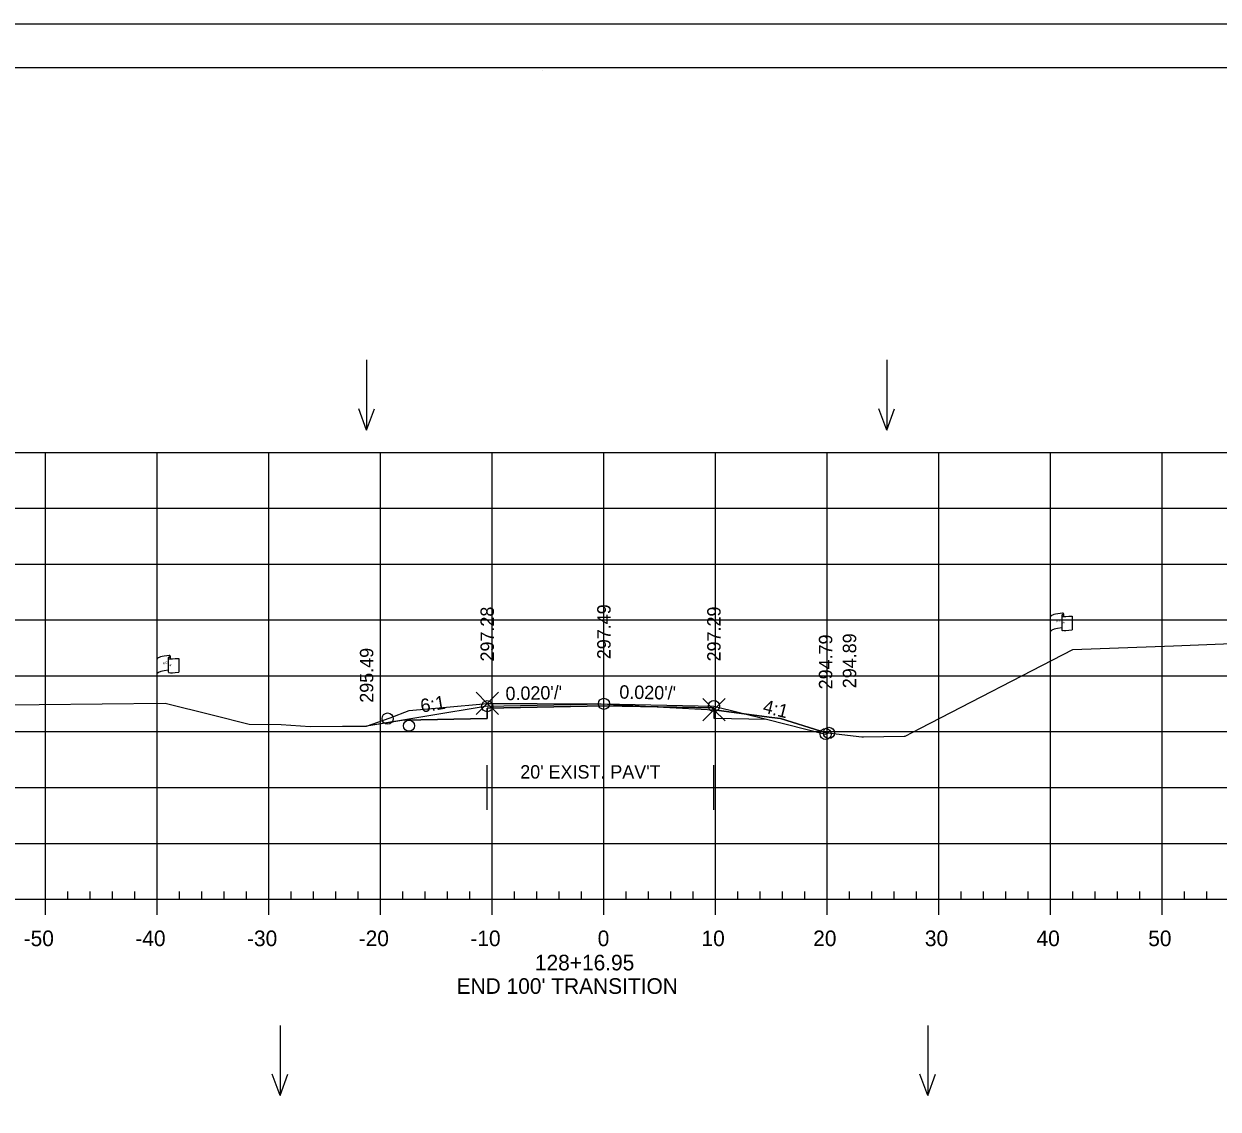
# Model space of a CAD drawing. Extents: x 1370843 to 1371177, y 380307 to 382654.
# Drawn here: x 1370961.8 to 1371068.7, y 382557 to 382654.2 of the extents above; entities that cross this region are included whole.
import ezdxf

# ---------------------------------------------------------------- set-up
doc = ezdxf.new("R2010")
doc.units = 0
for name, color, linetype in [('R_Axis', 7, 'Continuous'), ('R_Axis Annot', 7, 'Continuous'), ('R_Border', 7, 'Continuous'), ('R_Exist Surface', 7, 'Continuous'), ('R_Exist Surface Annot', 7, 'Continuous'), ('R_Fin Surface Annot', 7, 'Continuous'), ('R_Grid', 7, 'Continuous'), ('R_No Plot', 7, 'Continuous'), ('R_ROW', 7, 'Continuous'), ('R_Water Annot', 7, 'Continuous')]:
    doc.layers.add(name, color=color, linetype=linetype)

msp = doc.modelspace()

# ---------------------------------------------------------------- linework, layer by layer
at = {"layer": 'R_Axis'}
for p, q in [((1370868.71, 382575.83), (1371158.71, 382575.83)), ((1370963.71, 382574.43), (1370963.71, 382575.83)), ((1370965.71, 382575.83), (1370965.71, 382576.53)), ((1370967.71, 382575.83), (1370967.71, 382576.53)), ((1370969.71, 382575.83), (1370969.71, 382576.53)), ((1370971.71, 382575.83), (1370971.71, 382576.53)), ((1370973.71, 382574.43), (1370973.71, 382575.83)), ((1370975.71, 382575.83), (1370975.71, 382576.53)), ((1370977.71, 382575.83), (1370977.71, 382576.53)), ((1370979.71, 382575.83), (1370979.71, 382576.53)), ((1370981.71, 382575.83), (1370981.71, 382576.53)), ((1370983.71, 382574.43), (1370983.71, 382575.83)), ((1370985.71, 382575.83), (1370985.71, 382576.53)), ((1370987.71, 382575.83), (1370987.71, 382576.53)), ((1370989.71, 382575.83), (1370989.71, 382576.53)), ((1370991.71, 382575.83), (1370991.71, 382576.53)), ((1370993.71, 382574.43), (1370993.71, 382575.83)), ((1370995.71, 382575.83), (1370995.71, 382576.53)), ((1370997.71, 382575.83), (1370997.71, 382576.53)), ((1370999.71, 382575.83), (1370999.71, 382576.53)), ((1371001.71, 382575.83), (1371001.71, 382576.53)), ((1371003.71, 382574.43), (1371003.71, 382575.83)), ((1371005.71, 382575.83), (1371005.71, 382576.53)), ((1371007.71, 382575.83), (1371007.71, 382576.53)), ((1371009.71, 382575.83), (1371009.71, 382576.53)), ((1371011.71, 382575.83), (1371011.71, 382576.53)), ((1371013.71, 382574.43), (1371013.71, 382575.83)), ((1371015.71, 382575.83), (1371015.71, 382576.53)), ((1371017.71, 382575.83), (1371017.71, 382576.53)), ((1371019.71, 382575.83), (1371019.71, 382576.53)), ((1371021.71, 382575.83), (1371021.71, 382576.53)), ((1371023.71, 382574.43), (1371023.71, 382575.83)), ((1371025.71, 382575.83), (1371025.71, 382576.53)), ((1371027.71, 382575.83), (1371027.71, 382576.53)), ((1371029.71, 382575.83), (1371029.71, 382576.53)), ((1371031.71, 382575.83), (1371031.71, 382576.53)), ((1371033.71, 382574.43), (1371033.71, 382575.83)), ((1371035.71, 382575.83), (1371035.71, 382576.53)), ((1371037.71, 382575.83), (1371037.71, 382576.53)), ((1371039.71, 382575.83), (1371039.71, 382576.53)), ((1371041.71, 382575.83), (1371041.71, 382576.53)), ((1371043.71, 382574.43), (1371043.71, 382575.83)), ((1371045.71, 382575.83), (1371045.71, 382576.53)), ((1371047.71, 382575.83), (1371047.71, 382576.53)), ((1371049.71, 382575.83), (1371049.71, 382576.53)), ((1371051.71, 382575.83), (1371051.71, 382576.53)), ((1371053.71, 382574.43), (1371053.71, 382575.83)), ((1371055.71, 382575.83), (1371055.71, 382576.53)), ((1371057.71, 382575.83), (1371057.71, 382576.53)), ((1371059.71, 382575.83), (1371059.71, 382576.53)), ((1371061.71, 382575.83), (1371061.71, 382576.53)), ((1371063.71, 382574.43), (1371063.71, 382575.83)), ((1371065.71, 382575.83), (1371065.71, 382576.53)), ((1371067.71, 382575.83), (1371067.71, 382576.53))]:
    msp.add_line(p, q, dxfattribs=at)
at = {"layer": 'R_Border'}
for p, q in [((1370855.71, 382650.29), (1371171.89, 382650.29)), ((1371008.23, 382650.03), (1371008.23, 382650.03)), ((1371008.23, 382650.03), (1371008.23, 382650.03))]:
    msp.add_line(p, q, dxfattribs=at)
at = {"layer": 'R_Exist Surface'}
msp.add_lwpolyline([(1370954.77, 382593.19), (1370963.15, 382593.25), (1370974.42, 382593.39), (1370978.64, 382592.34), (1370981.93, 382591.51), (1370984.8, 382591.47), (1370987.41, 382591.3), (1370990.31, 382591.31), (1370992.46, 382591.32), (1370994.57, 382592.08), (1370996.27, 382592.73), (1370999.29, 382593), (1371003.26, 382593.36), (1371007.74, 382593.34), (1371013.45, 382593.33), (1371019.06, 382593.03), (1371023.56, 382592.79), (1371028.76, 382592.1), (1371029.51, 382592), (1371033.12, 382590.87), (1371033.5, 382590.76), (1371036.81, 382590.38), (1371036.94, 382590.36), (1371040.61, 382590.43), (1371040.68, 382590.43), (1371042.07, 382591.14), (1371055.69, 382598.19), (1371064.7, 382598.52), (1371098.98, 382599.88)], dxfattribs=at)
at = {"layer": 'R_Exist Surface Annot'}
for p, q in [((1371003.26, 382583.83), (1371003.26, 382587.83)), ((1371023.56, 382583.83), (1371023.56, 382587.83)), ((1371003.26, 382585.83), (1371023.56, 382585.83))]:
    msp.add_line(p, q, dxfattribs=at)
at = {"layer": 'R_Grid'}
for p, q in [((1370868.71, 382615.83), (1371158.71, 382615.83)), ((1370963.71, 382575.83), (1370963.71, 382615.83)), ((1370973.71, 382575.83), (1370973.71, 382615.83)), ((1370983.71, 382575.83), (1370983.71, 382615.83)), ((1370993.71, 382575.83), (1370993.71, 382615.83)), ((1371003.71, 382575.83), (1371003.71, 382615.83)), ((1371013.71, 382575.83), (1371013.71, 382615.83)), ((1371023.71, 382575.83), (1371023.71, 382615.83)), ((1371033.71, 382575.83), (1371033.71, 382615.83)), ((1371043.71, 382575.83), (1371043.71, 382615.83)), ((1371053.71, 382575.83), (1371053.71, 382615.83)), ((1371063.71, 382575.83), (1371063.71, 382615.83)), ((1370868.71, 382610.83), (1371158.71, 382610.83)), ((1370868.71, 382605.83), (1371158.71, 382605.83)), ((1370868.71, 382600.83), (1371158.71, 382600.83)), ((1370868.71, 382595.83), (1371158.71, 382595.83)), ((1370868.71, 382590.83), (1371158.71, 382590.83)), ((1370868.71, 382585.83), (1371158.71, 382585.83)), ((1370868.71, 382580.83), (1371158.71, 382580.83)), ((1370868.71, 382575.83), (1371158.71, 382575.83))]:
    msp.add_line(p, q, dxfattribs=at)
at = {"layer": 'R_No Plot'}
for p, q in [((1370843.31, 382654.18), (1371176.64, 382654.18)), ((1371003.26, 382593.11), (1370992.46, 382591.32))]:
    msp.add_line(p, q, dxfattribs=at)
for points in [[(1370843.3, 382654.18), (1371176.64, 382654.18), (1371176.64, 382440.85), (1370843.3, 382440.85)], [(1371089.63, 382650.29), (1371089.63, 382640.41), (1371125.36, 382640.41), (1371125.36, 382637.49), (1371148.56, 382637.49), (1371148.56, 382613.16), (1371171.89, 382613.16), (1371171.89, 382444.83), (1370855.71, 382444.83), (1370855.71, 382650.29)], [(1370992.46, 382591.32), (1370994.57, 382592.08), (1370996.27, 382592.73), (1370999.29, 382593), (1371003.26, 382593.36), (1371007.74, 382593.34), (1371013.45, 382593.33), (1371018.58, 382593.05), (1371013.71, 382593.15), (1371003.26, 382592.94), (1371003.26, 382592.02), (1370995.82, 382591.87)], [(1371018.58, 382593.05), (1371019.06, 382593.03), (1371023.56, 382592.79), (1371023.56, 382592.95)], [(1371023.56, 382592.79), (1371023.56, 382592.04), (1371028.27, 382591.94), (1371033.56, 382590.62), (1371033.86, 382590.72), (1371033.5, 382590.76), (1371033.12, 382590.87), (1371029.51, 382592), (1371028.76, 382592.1)]]:
    msp.add_lwpolyline(points, close=True, dxfattribs=at)
for points in [[(1371003.26, 382593.36), (1371002.26, 382594.36), (1371003.26, 382593.36), (1371002.26, 382592.36), (1371003.26, 382593.36), (1371004.26, 382592.36), (1371003.26, 382593.36), (1371004.26, 382594.36)], [(1370995.82, 382591.87), (1371003.26, 382592.02), (1371003.26, 382592.94), (1371013.71, 382593.15), (1371023.56, 382592.95), (1371023.56, 382592.04), (1371028.27, 382591.94)], [(1371003.26, 382593.11), (1371013.71, 382593.32), (1371023.56, 382593.12), (1371028.27, 382591.94), (1371033.56, 382590.62), (1371033.86, 382590.72)], [(1371023.56, 382592.79), (1371022.56, 382593.79), (1371023.56, 382592.79), (1371022.56, 382591.79), (1371023.56, 382592.79), (1371024.56, 382591.79), (1371023.56, 382592.79), (1371024.56, 382593.79)]]:
    msp.add_lwpolyline(points, dxfattribs=at)
for centre in [(1371003.26, 382593.11), (1371003.26, 382593.11), (1371013.71, 382593.32), (1371023.56, 382593.12), (1371023.56, 382593.12), (1370994.34, 382592), (1370996.26, 382591.36), (1371033.56, 382590.62), (1371033.86, 382590.72)]:
    msp.add_circle(centre, 0.5, dxfattribs=at)
at = {"layer": 'R_ROW'}
for p, q in [((1371054.87, 382601.37), (1371054.87, 382601.13)), ((1371053.71, 382597.17), (1371053.71, 382601.12)), ((1371054.7, 382601.21), (1371054.7, 382601.2)), ((1371054.7, 382601.2), (1371054.7, 382599.97)), ((1371055.64, 382601.17), (1371055.64, 382599.93)), ((1370973.71, 382593.38), (1370973.71, 382597.33)), ((1370974.7, 382597.43), (1370974.7, 382597.41)), ((1370974.7, 382597.41), (1370974.7, 382596.19)), ((1370974.87, 382597.58), (1370974.87, 382597.34)), ((1370975.64, 382597.39), (1370975.64, 382596.15))]:
    msp.add_line(p, q, dxfattribs=at)
for centre, radius, start, end in [((1371054.79, 382601.37), 0.0783, 263.0712, 93.9564), ((1371054.78, 382601.21), 0.078, 88.6458, 274.2828), ((1371054.78, 382599.97), 0.0783, 180, 273.9564), ((1370974.78, 382597.43), 0.078, 88.6458, 274.2828), ((1370974.79, 382597.58), 0.0783, 263.0712, 93.9564), ((1370974.78, 382596.19), 0.0783, 180, 273.9564)]:
    msp.add_arc(centre, radius, start, end, dxfattribs=at)
for centre, major_axis, ratio, start_param, end_param in [((1371055.29, 382601.16), (-1.58, -0.04), 0.19887, 5.030368, 6.283185), ((1371056, 382601.28), (-1.23, -0.13), 0.052933, 0.159456, 1.268315), ((1371055.29, 382599.84), (-1.58, -0.04), 0.19887, 5.083035, 6.194897), ((1371056, 382600.04), (-1.23, -0.13), 0.052933, 0.159456, 1.268315), ((1370975.29, 382597.37), (-1.58, -0.04), 0.19887, 5.030368, 6.283185), ((1370976, 382597.49), (-1.23, -0.13), 0.052933, 0.159456, 1.268315), ((1370975.29, 382596.06), (-1.58, -0.04), 0.19887, 5.083035, 6.194897), ((1370976, 382596.25), (-1.23, -0.13), 0.052933, 0.159456, 1.268315)]:
    msp.add_ellipse(centre, major_axis=major_axis, ratio=ratio, start_param=start_param, end_param=end_param, dxfattribs=at)
at = {"layer": 'R_Water Annot'}
for p, q in [((1370992.46, 382624.1), (1370992.46, 382617.81)), ((1371039.04, 382624.1), (1371039.04, 382617.81)), ((1370992.46, 382617.81), (1370991.76, 382619.73)), ((1370992.46, 382617.81), (1370993.16, 382619.73)), ((1371039.04, 382617.81), (1371038.34, 382619.73)), ((1371039.04, 382617.81), (1371039.74, 382619.73)), ((1370984.71, 382564.54), (1370984.71, 382558.26)), ((1371042.71, 382564.54), (1371042.71, 382558.26)), ((1370984.71, 382558.26), (1370984.01, 382560.18)), ((1370984.71, 382558.26), (1370985.41, 382560.18)), ((1371042.71, 382558.26), (1371042.01, 382560.18)), ((1371042.71, 382558.26), (1371043.41, 382560.18))]:
    msp.add_line(p, q, dxfattribs=at)

# ---------------------------------------------------------------- texts
at = {"layer": 'R_Axis Annot'}
for s, p in [('-50', (1370961.75, 382571.63)), ('-40', (1370971.75, 382571.63)), ('-30', (1370981.75, 382571.63)), ('-20', (1370991.75, 382571.63)), ('-10', (1371001.75, 382571.63)), ('0', (1371013.15, 382571.63)), ('10', (1371022.45, 382571.63)), ('20', (1371032.45, 382571.63)), ('30', (1371042.45, 382571.63)), ('40', (1371052.45, 382571.63)), ('50', (1371062.45, 382571.63)), ('128+16.95', (1371007.53, 382569.46)), ("END 100' TRANSITION", (1371000.52, 382567.36))]:
    msp.add_text(s, height=1.4, dxfattribs=at).set_placement(p)
at = {"layer": 'R_Exist Surface Annot'}
msp.add_text("20' EXIST. PAV'T", height=1.2, dxfattribs=at).set_placement((1371006.22, 382586.63))
at = {"layer": 'R_Fin Surface Annot'}
for s, p in [('297.28', (1371003.86, 382597.11)), ('297.49', (1371014.31, 382597.32)), ('297.29', (1371024.16, 382597.12))]:
    msp.add_text(s, height=1.2, rotation=90, dxfattribs=at).set_placement(p)
at = {"layer": 'R_No Plot'}
for s, rotation, p in [('297.28', 90, (1371003.86, 382597.11)), ('297.29', 90, (1371024.16, 382597.12)), ('294.79', 90, (1371034.16, 382594.62)), ('294.89', 90, (1371036.3, 382594.72)), ('295.49', 90, (1370993.06, 382593.42)), ("0.020'/'", 1.1458, (1371004.91, 382593.64)), ("0.020'/'", 358.8542, (1371015.08, 382593.79)), ('6:1', 9.4089, (1370997.38, 382592.53)), ('4:1', 345.9638, (1371027.87, 382592.56))]:
    msp.add_text(s, height=1.2, rotation=rotation, dxfattribs=at).set_placement(p)
at = {"layer": 'R_ROW'}
for s, height, rotation, p in [('R ', 0.2, 9.9884, (1371054.23, 382600.62)), (' O', 0.2, 9.9884, (1371054.37, 382600.66)), ('W', 0.2, 351.1788, (1371054.7, 382600.5)), ('DWB 11-9-07', 0.001, 90, (1371054.87, 382601.13)), ('DWB 11-9-07', 0.001, 5.0717, (1371055.63, 382599.93)), ('R ', 0.2, 9.9884, (1370974.23, 382596.83)), (' O', 0.2, 9.9884, (1370974.37, 382596.88)), ('DWB 11-9-07', 0.001, 90, (1370974.87, 382597.34)), ('DWB 11-9-07', 0.001, 90, (1371053.71, 382597.17)), ('W', 0.2, 351.1788, (1370974.7, 382596.71)), ('DWB 11-9-07', 0.001, 5.0717, (1370975.63, 382596.15)), ('DWB 11-9-07', 0.001, 90, (1370973.71, 382593.38))]:
    msp.add_text(s, height=height, rotation=rotation, dxfattribs=at).set_placement(p)

doc.saveas('drawing.dxf')
